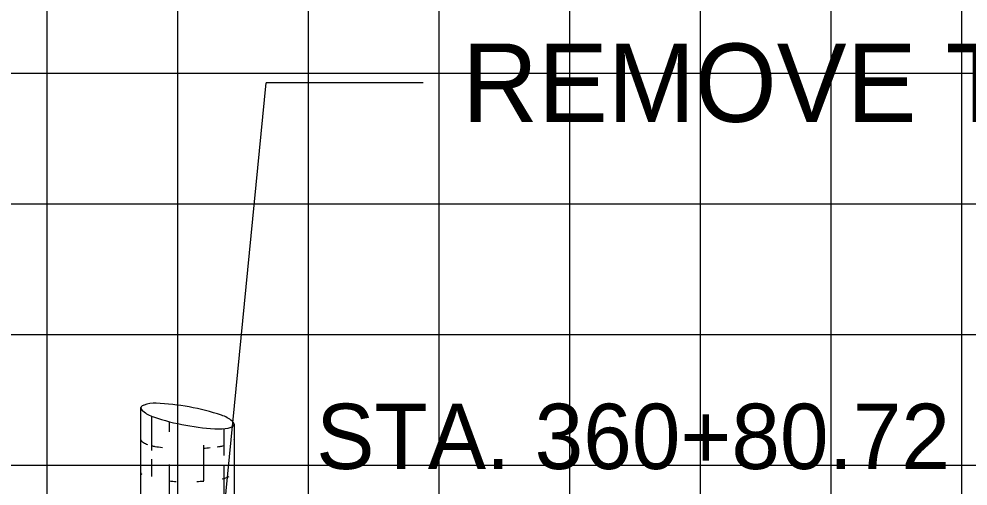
# Model space of a CAD drawing. Extents: x 1146525 to 1146695, y 608981 to 609091.
# Drawn here: x 1146572.45 to 1146579.72, y 609035.17 to 609038.75 of the extents above; entities that cross this region are included whole.
import ezdxf

# ---------------------------------------------------------------- set-up
doc = ezdxf.new("R2010")
doc.units = 0
for name, color, linetype in [('ANNOTATION', 7, 'Continuous'), ('D_Text_Monospaced', 7, 'Continuous'), ('MAJOR', 7, 'Continuous'), ('MINOR', 7, 'Continuous'), ('S_Trees_Conifer_NonPay', 7, 'Continuous')]:
    doc.layers.add(name, color=color, linetype=linetype)

msp = doc.modelspace()

# ---------------------------------------------------------------- linework, layer by layer
at = {"layer": 'ANNOTATION'}
for p in [(1146573.877, 609033.4904), (1146575.5467, 609038.2623)]:
    msp.add_line(p, (1146574.3467, 609038.2623), dxfattribs=at)
at = {"layer": 'MAJOR'}
for p, q in [((1146572.6713, 609020.3351), (1146572.6713, 609045.3351)), ((1146577.6713, 609020.3351), (1146577.6713, 609045.3351)), ((1146537.6713, 609035.3351), (1146677.6713, 609035.3351))]:
    msp.add_line(p, q, dxfattribs=at)
at = {"layer": 'MINOR'}
for p, q in [((1146573.6713, 609020.3351), (1146573.6713, 609045.3351)), ((1146574.6713, 609020.3351), (1146574.6713, 609045.3351)), ((1146575.6713, 609020.3351), (1146575.6713, 609045.3351)), ((1146576.6713, 609020.3351), (1146576.6713, 609045.3351)), ((1146578.6713, 609020.3351), (1146578.6713, 609045.3351)), ((1146579.6713, 609020.3351), (1146579.6713, 609045.3351)), ((1146537.6713, 609038.3351), (1146677.6713, 609038.3351)), ((1146537.6713, 609037.3351), (1146677.6713, 609037.3351)), ((1146537.6713, 609036.3351), (1146677.6713, 609036.3351))]:
    msp.add_line(p, q, dxfattribs=at)
at = {"layer": 'S_Trees_Conifer_NonPay'}
for p, q in [((1146573.6036, 609035.668), (1146573.6036, 609035.5893)), ((1146574.0223, 609035.6129), (1146574.0223, 609035.4075)), ((1146573.8655, 609035.4882), (1146573.8655, 609035.2146)), ((1146573.4691, 609035.3793), (1146573.4691, 609035.2487)), ((1146573.6036, 609035.3399), (1146573.6036, 609035.0145)), ((1146574.0223, 609035.3347), (1146574.0223, 609035.0033))]:
    msp.add_line(p, q, dxfattribs=at)
for points in [[(1146573.3582, 609033.6634), (1146573.2421, 609033.6726), (1146573.334, 609033.798), (1146573.3674, 609034.3386), (1146573.3878, 609034.8557), (1146573.3878, 609035.775)], [(1146573.4691, 609035.7087), (1146573.4691, 609035.6116), (1146573.4691, 609035.4469)], [(1146574.101, 609035.647), (1146574.101, 609033.9292), (1146574.1706, 609033.6726), (1146574.29, 609033.6385), (1146574.0735, 609033.6221), (1146573.914, 609033.5637), (1146573.7047, 609033.6221), (1146573.4422, 609033.5749), (1146573.2362, 609033.5808), (1146573.3878, 609033.6838), (1146573.4593, 609033.8373)]]:
    msp.add_lwpolyline(points, dxfattribs=at)
for centre, radius, start, end in [((1146573.4061, 609035.7706), 0.0186, 139.62016, 153.56698), ((1146573.4119, 609035.7656), 0.0263, 120.85978, 139.62016), ((1146573.4358, 609035.7256), 0.0729, 109.62016, 120.85978), ((1146573.4937, 609035.5634), 0.2452, 87.6349, 109.62016), ((1146573.4285, 609033.9845), 1.8254, 79.62016, 87.6349), ((1146573.402, 609035.7726), 0.0141, 169.62016, 185.67333), ((1146573.4065, 609035.7731), 0.0186, 185.67333, 199.62016), ((1146573.402, 609035.7726), 0.0141, 153.56698, 169.62016), ((1146573.4138, 609035.7757), 0.0263, 199.62016, 218.38053), ((1146573.4503, 609035.8046), 0.0729, 218.38053, 229.62016), ((1146573.5619, 609035.9358), 0.2452, 229.62016, 251.60541), ((1146573.4285, 609033.9845), 1.8254, 71.60541, 79.62016), ((1146573.9271, 609035.484), 0.2452, 49.62016, 71.60541), ((1146574.0606, 609037.4353), 1.8254, 251.60541, 259.62016), ((1146574.0606, 609037.4353), 1.8254, 259.62016, 267.6349), ((1146574.0387, 609035.6152), 0.0729, 38.38053, 49.62016), ((1146574.0771, 609035.6542), 0.0263, 300.85978, 319.62016), ((1146574.0752, 609035.6441), 0.0263, 19.62016, 38.38053), ((1146574.083, 609035.6492), 0.0186, 319.62016, 333.56698), ((1146574.087, 609035.6472), 0.0141, 333.56698, 349.62016), ((1146574.0825, 609035.6467), 0.0186, 5.67333, 19.62016), ((1146574.087, 609035.6472), 0.0141, 349.62016, 5.67333), ((1146573.9953, 609035.8565), 0.2452, 267.6349, 289.62016), ((1146574.0532, 609035.6942), 0.0729, 289.62016, 300.85978), ((1146573.4061, 609035.5326), 0.0189, 196.05154, 210), ((1146573.4129, 609035.5365), 0.0267, 210, 228.74941), ((1146573.4439, 609035.572), 0.0738, 228.74941, 240), ((1146573.5293, 609035.7198), 0.2446, 240, 248.23465), ((1146574.0862, 609035.5314), 0.0143, 343.94846, 360), ((1146573.5293, 609035.7198), 0.2446, 255.81408, 261.8968), ((1146573.744, 609037.2274), 1.7673, 261.8968, 263.75513), ((1146573.744, 609037.2274), 1.7673, 273.95007, 275.67326), ((1146573.744, 609037.2274), 1.7673, 277.39504, 278.1032), ((1146573.9586, 609035.7198), 0.2446, 278.1032, 285.15392), ((1146573.4043, 609035.2804), 0.0189, 196.05154, 210), ((1146573.4111, 609035.2843), 0.0267, 210, 228.74941), ((1146573.7422, 609036.9751), 1.7673, 265.51533, 267.27788), ((1146573.7422, 609036.9751), 1.7673, 272.40382, 274.10088), ((1146573.9568, 609035.4676), 0.2446, 282.46254, 295.68518)]:
    msp.add_arc(centre, radius, start, end, dxfattribs=at)

# ---------------------------------------------------------------- texts
at = {"layer": 'ANNOTATION'}
msp.add_text('REMOVE TREES', height=0.599999, dxfattribs=at).set_placement((1146575.8467, 609037.9623))
at = {"layer": 'D_Text_Monospaced'}
msp.add_text('STA. 360+80.72', height=0.49998, dxfattribs=at).set_placement((1146574.7292, 609035.3048))

doc.saveas('drawing.dxf')
